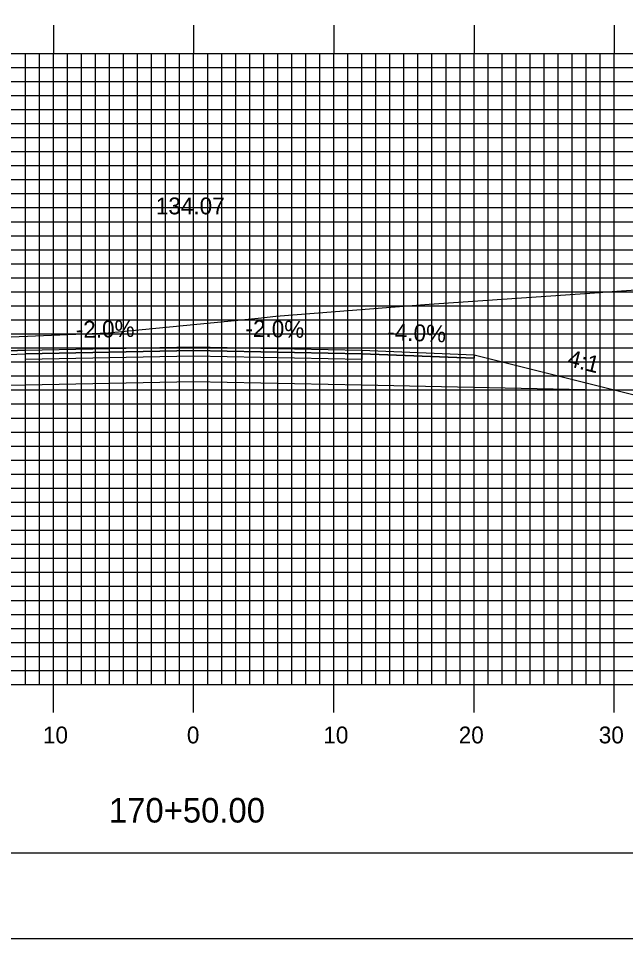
# Model space of a CAD drawing. Extents: x 1782647 to 1782990, y 442591 to 442811.
# Drawn here: x 1782800.4 to 1782843.8, y 442590.5 to 442656.2 of the extents above; entities that cross this region are included whole.
import ezdxf

# ---------------------------------------------------------------- set-up
doc = ezdxf.new("R2010")
doc.units = 0
for name, color, linetype in [('ANNOTATION', 7, 'Continuous'), ('BORDER', 7, 'Continuous'), ('D_Roadway_Centerline', 7, 'Continuous'), ('D_Roadway_Centerline_Text', 7, 'Continuous'), ('D_Roadway_Edge_Shoulder', 7, 'Continuous'), ('D_Roadway_Edge_TW', 7, 'Continuous'), ('D_Roadway_Pavement', 7, 'Continuous'), ('D_Roadway_SlopeLines', 7, 'Continuous'), ('D_Roadway_SubGrade', 7, 'Continuous'), ('H_V ANNOTATION', 7, 'Continuous'), ('MAJOR', 7, 'Continuous'), ('MINOR', 7, 'Continuous'), ('PLOT BOUNDARY', 7, 'Continuous'), ('S_Roadway_Centerline', 7, 'Continuous')]:
    doc.layers.add(name, color=color, linetype=linetype)

msp = doc.modelspace()

# ---------------------------------------------------------------- linework, layer by layer
at = {"layer": 'BORDER'}
msp.add_lwpolyline([(1782663.347, 442596.665), (1782983.347, 442596.665), (1782983.347, 442806.665), (1782663.347, 442806.665)], close=True, dxfattribs=at)
at = {"layer": 'D_Roadway_Centerline'}
msp.add_lwpolyline([(1782771.185, 442630.8), (1782772.435, 442630.887), (1782773.685, 442630.771), (1782774.935, 442630.451), (1782776.185, 442629.928), (1782778.773, 442628.634), (1782782.773, 442629.634), (1782792.947, 442632.178), (1782800.947, 442632.498), (1782812.947, 442632.738), (1782824.947, 442632.498), (1782832.947, 442632.178), (1782843.121, 442629.634), (1782847.121, 442628.634), (1782864.105, 442637.126), (1782865.355, 442637.684), (1782866.605, 442638.106), (1782867.855, 442638.394), (1782869.105, 442638.546)], dxfattribs=at)
at = {"layer": 'D_Roadway_Edge_Shoulder'}
for points in [[(1782800.947, 442632.498), (1782792.947, 442632.178), (1782792.947, 442631.928), (1782800.947, 442632.248)], [(1782824.947, 442632.498), (1782832.947, 442632.178), (1782832.947, 442631.928), (1782824.947, 442632.248)]]:
    msp.add_lwpolyline(points, close=True, dxfattribs=at)
at = {"layer": 'D_Roadway_Edge_TW'}
msp.add_lwpolyline([(1782800.947, 442632.248), (1782800.947, 442632.498), (1782812.947, 442632.738), (1782824.947, 442632.498), (1782824.947, 442632.248), (1782812.947, 442632.488)], close=True, dxfattribs=at)
at = {"layer": 'D_Roadway_Pavement'}
msp.add_lwpolyline([(1782800.947, 442631.831), (1782800.947, 442632.248), (1782812.947, 442632.488), (1782824.947, 442632.248), (1782824.947, 442631.831), (1782812.947, 442632.071)], close=True, dxfattribs=at)
at = {"layer": 'D_Roadway_SlopeLines'}
msp.add_lwpolyline([(1782832.947, 442632.178), (1782847.121, 442628.634)], dxfattribs=at)
at = {"layer": 'D_Roadway_SubGrade'}
msp.add_lwpolyline([(1782800.947, 442629.998), (1782782.773, 442629.634), (1782792.947, 442632.178), (1782792.947, 442631.928), (1782800.947, 442632.248), (1782812.947, 442632.488), (1782824.947, 442632.248), (1782832.947, 442631.928), (1782832.947, 442632.178), (1782843.121, 442629.634), (1782824.947, 442629.998), (1782812.947, 442630.238)], close=True, dxfattribs=at)
at = {"layer": 'MAJOR'}
for p, q in [((1782802.947, 442655.669), (1782802.947, 442653.665)), ((1782812.947, 442655.669), (1782812.947, 442653.665)), ((1782822.947, 442655.669), (1782822.947, 442653.665)), ((1782832.947, 442655.669), (1782832.947, 442653.665)), ((1782842.947, 442655.669), (1782842.947, 442653.665)), ((1782672.947, 442653.665), (1782952.947, 442653.665)), ((1782672.947, 442653.665), (1782952.947, 442653.665)), ((1782802.947, 442608.665), (1782802.947, 442653.665)), ((1782812.947, 442608.665), (1782812.947, 442653.665)), ((1782822.947, 442608.665), (1782822.947, 442653.665)), ((1782832.947, 442608.665), (1782832.947, 442653.665)), ((1782842.947, 442608.665), (1782842.947, 442653.665)), ((1782672.947, 442648.665), (1782952.947, 442648.665)), ((1782672.947, 442643.665), (1782952.947, 442643.665)), ((1782672.947, 442638.665), (1782952.947, 442638.665)), ((1782672.947, 442633.665), (1782952.947, 442633.665)), ((1782672.947, 442628.665), (1782952.947, 442628.665)), ((1782672.947, 442623.665), (1782952.947, 442623.665)), ((1782672.947, 442618.665), (1782952.947, 442618.665)), ((1782672.947, 442613.665), (1782952.947, 442613.665)), ((1782672.947, 442608.665), (1782952.947, 442608.665)), ((1782672.947, 442608.665), (1782952.947, 442608.665)), ((1782802.947, 442606.661), (1782802.947, 442608.665)), ((1782812.947, 442606.661), (1782812.947, 442608.665)), ((1782822.947, 442606.661), (1782822.947, 442608.665)), ((1782832.947, 442606.661), (1782832.947, 442608.665)), ((1782842.947, 442606.661), (1782842.947, 442608.665))]:
    msp.add_line(p, q, dxfattribs=at)
at = {"layer": 'MINOR'}
for p, q in [((1782800.947, 442608.665), (1782800.947, 442653.665)), ((1782801.947, 442608.665), (1782801.947, 442653.665)), ((1782803.947, 442608.665), (1782803.947, 442653.665)), ((1782804.947, 442608.665), (1782804.947, 442653.665)), ((1782805.947, 442608.665), (1782805.947, 442653.665)), ((1782806.947, 442608.665), (1782806.947, 442653.665)), ((1782807.947, 442608.665), (1782807.947, 442653.665)), ((1782808.947, 442608.665), (1782808.947, 442653.665)), ((1782809.947, 442608.665), (1782809.947, 442653.665)), ((1782810.947, 442608.665), (1782810.947, 442653.665)), ((1782811.947, 442608.665), (1782811.947, 442653.665)), ((1782813.947, 442608.665), (1782813.947, 442653.665)), ((1782814.947, 442608.665), (1782814.947, 442653.665)), ((1782815.947, 442608.665), (1782815.947, 442653.665)), ((1782816.947, 442608.665), (1782816.947, 442653.665)), ((1782817.947, 442608.665), (1782817.947, 442653.665)), ((1782818.947, 442608.665), (1782818.947, 442653.665)), ((1782819.947, 442608.665), (1782819.947, 442653.665)), ((1782820.947, 442608.665), (1782820.947, 442653.665)), ((1782821.947, 442608.665), (1782821.947, 442653.665)), ((1782823.947, 442608.665), (1782823.947, 442653.665)), ((1782824.947, 442608.665), (1782824.947, 442653.665)), ((1782825.947, 442608.665), (1782825.947, 442653.665)), ((1782826.947, 442608.665), (1782826.947, 442653.665)), ((1782827.947, 442608.665), (1782827.947, 442653.665)), ((1782828.947, 442608.665), (1782828.947, 442653.665)), ((1782829.947, 442608.665), (1782829.947, 442653.665)), ((1782830.947, 442608.665), (1782830.947, 442653.665)), ((1782831.947, 442608.665), (1782831.947, 442653.665)), ((1782833.947, 442608.665), (1782833.947, 442653.665)), ((1782834.947, 442608.665), (1782834.947, 442653.665)), ((1782835.947, 442608.665), (1782835.947, 442653.665)), ((1782836.947, 442608.665), (1782836.947, 442653.665)), ((1782837.947, 442608.665), (1782837.947, 442653.665)), ((1782838.947, 442608.665), (1782838.947, 442653.665)), ((1782839.947, 442608.665), (1782839.947, 442653.665)), ((1782840.947, 442608.665), (1782840.947, 442653.665)), ((1782841.947, 442608.665), (1782841.947, 442653.665)), ((1782672.947, 442652.665), (1782952.947, 442652.665)), ((1782672.947, 442651.665), (1782952.947, 442651.665)), ((1782672.947, 442650.665), (1782952.947, 442650.665)), ((1782672.947, 442649.665), (1782952.947, 442649.665)), ((1782672.947, 442647.665), (1782952.947, 442647.665)), ((1782672.947, 442646.665), (1782952.947, 442646.665)), ((1782672.947, 442645.665), (1782952.947, 442645.665)), ((1782672.947, 442644.665), (1782952.947, 442644.665)), ((1782672.947, 442642.665), (1782952.947, 442642.665)), ((1782672.947, 442641.665), (1782952.947, 442641.665)), ((1782672.947, 442640.665), (1782952.947, 442640.665)), ((1782672.947, 442639.665), (1782952.947, 442639.665)), ((1782672.947, 442637.665), (1782952.947, 442637.665)), ((1782672.947, 442636.665), (1782952.947, 442636.665)), ((1782672.947, 442635.665), (1782952.947, 442635.665)), ((1782672.947, 442634.665), (1782952.947, 442634.665)), ((1782672.947, 442632.665), (1782952.947, 442632.665)), ((1782672.947, 442631.665), (1782952.947, 442631.665)), ((1782672.947, 442630.665), (1782952.947, 442630.665)), ((1782672.947, 442629.665), (1782952.947, 442629.665)), ((1782672.947, 442627.665), (1782952.947, 442627.665)), ((1782672.947, 442626.665), (1782952.947, 442626.665)), ((1782672.947, 442625.665), (1782952.947, 442625.665)), ((1782672.947, 442624.665), (1782952.947, 442624.665)), ((1782672.947, 442622.665), (1782952.947, 442622.665)), ((1782672.947, 442621.665), (1782952.947, 442621.665)), ((1782672.947, 442620.665), (1782952.947, 442620.665)), ((1782672.947, 442619.665), (1782952.947, 442619.665)), ((1782672.947, 442617.665), (1782952.947, 442617.665)), ((1782672.947, 442616.665), (1782952.947, 442616.665)), ((1782672.947, 442615.665), (1782952.947, 442615.665)), ((1782672.947, 442614.665), (1782952.947, 442614.665)), ((1782672.947, 442612.665), (1782952.947, 442612.665)), ((1782672.947, 442611.665), (1782952.947, 442611.665)), ((1782672.947, 442610.665), (1782952.947, 442610.665)), ((1782672.947, 442609.665), (1782952.947, 442609.665))]:
    msp.add_line(p, q, dxfattribs=at)
at = {"layer": 'PLOT BOUNDARY'}
msp.add_lwpolyline([(1782647.16, 442590.547), (1782987.16, 442590.547), (1782987.16, 442810.547), (1782647.16, 442810.547)], close=True, dxfattribs=at)
at = {"layer": 'S_Roadway_Centerline'}
msp.add_lwpolyline([(1782759.409, 442628.584), (1782769.904, 442630.592), (1782771.644, 442630.875), (1782773.198, 442631.131), (1782791.798, 442632.903), (1782797.041, 442633.325), (1782806.857, 442633.739), (1782816.845, 442634.722), (1782817.791, 442634.815), (1782818.812, 442634.918), (1782829.734, 442635.795), (1782841.885, 442636.625), (1782842.013, 442636.634), (1782842.143, 442636.643), (1782863.277, 442638.125), (1782865.446, 442638.297), (1782875.481, 442638.98), (1782886.179, 442639.988), (1782898.169, 442641.087)], dxfattribs=at)

# ---------------------------------------------------------------- texts
at = {"layer": 'ANNOTATION'}
for s, rotation, p in [('-2.0%', 1.14576, (1782804.553, 442633.37)), ('-2.0%', 358.85424, (1782816.633, 442633.464)), ('-4.0%', 357.70939, (1782826.739, 442633.228)), ('4:1', 345.96376, (1782839.54, 442631.391))]:
    msp.add_text(s, height=1.2, rotation=rotation, dxfattribs=at).set_placement(p)
at = {"layer": 'D_Roadway_Centerline'}
for s, p in [('C', (1782812.942, 442632.738)), ('L', (1782812.947, 442632.73))]:
    msp.add_text(s, height=0.0146, dxfattribs=at).set_placement(p)
at = {"layer": 'D_Roadway_Centerline_Text'}
msp.add_text('134.07', height=1.2, dxfattribs=at).set_placement((1782810.25, 442642.188))
at = {"layer": 'H_V ANNOTATION'}
for s, height, p in [('10', 1.2, (1782802.198, 442604.465)), ('0', 1.2, (1782812.465, 442604.465)), ('10', 1.2, (1782822.198, 442604.465)), ('20', 1.2, (1782831.855, 442604.465)), ('30', 1.2, (1782841.844, 442604.465)), ('170+50.00', 1.75, (1782806.907, 442598.821))]:
    msp.add_text(s, height=height, dxfattribs=at).set_placement(p)

doc.saveas('drawing.dxf')
